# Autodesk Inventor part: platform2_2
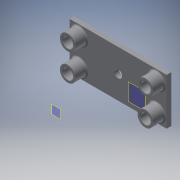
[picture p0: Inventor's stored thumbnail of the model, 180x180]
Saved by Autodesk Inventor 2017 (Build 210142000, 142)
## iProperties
Created: 2017-05
Part Number: platform2_2
Material: Generic
Document SubType Name: Modeling
Designer: 1717440
Density: 1 g/cm^3
Appearance: Default
Author: 1717440
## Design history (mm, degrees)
workplane "Work Plane1"
workplane "Work Plane4"
workplane "Work Plane2"
workplane "Work Plane3"
sketch "Sketch2"
  geometry: L1 (38.448, -43.362)-(38.448, 16.638); L2 (-86.552, 16.638)-(-86.552, -43.362); L3 (38.448, 16.638)-(-86.552, -43.362); L4 (-86.552, 16.638)-(38.448, -43.362); L5 (38.448, -43.362)-(-86.552, -43.362); L6 (38.448, 16.638)-(-86.552, 16.638); L7 (-25.603, -14.224)-(-22.5, -14.224); L8 (-22.5, -14.224)-(-22.5, -12.5); L9 (-22.5, -12.5)-(-25.603, -12.5); L10 (-25.603, -12.5)-(-25.603, -14.224); L11 (-22.5, -14.224)-(-25.603, -12.5); 2 further points
  constraints: 22 end point, 3 horizontal, 3 perpendicular, 2 midpoint, 2 parallel
  dimensions: "d11" = 125 distance of L1.start L2.end; "d12" = 60 distance of L2.start L2.end
extrude "Extrusion7" join sketch "Sketch2" distance "d20" = 6; taper "d21" = 0 deg
workplane "Work Plane5"
sketch "Sketch7"
  geometry: L1 (38.448, 43.362)-(38.448, -16.638) reference; L2 (-86.552, 43.362)-(38.448, 43.362) reference; L3 (-86.552, -16.638)-(-86.552, 43.362) reference; L4 (38.448, -16.638)-(-86.552, -16.638) reference; L5 (-74.052, 30.862)-(25.948, 30.862); L6 (25.948, 30.862)-(25.948, -4.138); L7 (25.948, -4.138)-(-74.052, -4.138); L8 (-74.052, -4.138)-(-74.052, 30.862); C1 r 6.425 at (-74.052, 30.862); C2 r 6.425 at (25.948, -4.138); C3 r 6.425 at (-74.052, -4.138); C4 r 6.425 at (25.948, 30.862); C5 r 10 at (-74.052, -4.138); C6 r 10 at (-74.052, 30.862); C7 r 10 at (25.948, 30.862); C8 r 10 at (25.948, -4.138); 1 further point
  constraints: 9 coincident, 8 centre point, 8 end point, 1 point on line, 3 other
  dimensions: "d25" = 12.5 distance between parallel lines of L3 L8; "d26" = 12.85 diameter of C1 (= d28); "d27" = 12.85 diameter of C2 (= d28); "d28" = 12.85 diameter of C3; "d29" = 12.85 diameter of C4 (= d28); "d33" = 20 diameter of C5; "d34" = 20 diameter of C6; "d35" = 20 diameter of C7; "d36" = 20 diameter of C8
workplane "Work Plane6"
extrude "Extrusion10" join sketch "Sketch7" distance "d37" = 15; taper "d38" = 0 deg
fillet "Fillet3" dims "d39" = 2
fillet "Fillet4" dims "d40" = 1
sketch "Sketch8"
  geometry: L1 (38.448, 16.638)-(-86.552, 16.638) reference; L2 (38.448, 16.638)-(-86.552, 16.638) reference; L3 (38.448, -43.362)-(33.448, -43.362); L4 (-86.552, -43.362)-(38.448, -43.362) reference; L5 (-86.552, 16.638)-(-86.552, -43.362) reference; L6 (33.448, -43.362)-(-86.552, 16.638); L7 (38.448, 16.638)-(33.448, 16.638); L8 (33.448, 16.638)-(-86.552, -43.362); C1 r 5.1 at (-26.552, -13.362); 1 further point
  constraints: 8 end point, 2 point on line, 1 centre point, 1 midpoint
  dimensions: "d43" = 10.2 diameter of C1; "d49" = 5 distance of L3.start L3.end; "d50" = 5 distance of L1.start L7.end
extrude "Extrusion11" cut sketch "Sketch8" distance "d41" = 16; taper "d42" = 0 deg
sketch "Sketch9"
  geometry: L1 (-86.552, 16.638)-(-86.552, -43.362) reference; L2 (38.448, 16.638)-(-86.552, 16.638) reference; L3 (38.448, 16.638)-(-86.552, 16.638); L4 (-86.552, 16.638)-(-86.552, 9.338); L5 (-86.552, 9.338)-(38.448, 9.338); L6 (38.448, 9.338)-(38.448, 16.638); L7 (38.448, -43.362)-(38.448, 16.638) reference; L8 (38.448, -43.362)-(-86.552, -43.362); L9 (-86.552, -43.362)-(-86.552, -36.062); L10 (-86.552, -36.062)-(38.448, -36.062); L11 (38.448, -36.062)-(38.448, -43.362); 1 further point
  constraints: 16 end point, 4 parallel, 2 horizontal, 2 perpendicular, 2 point on line
  dimensions: "d44" = 7.3 distance of L4.end L3.end; "d45" = 7.3 distance of L8.end L9.end
extrude "Extrusion12" join sketch "Sketch9" distance "d46" = 5; taper "d47" = 0 deg
fillet "Fillet5" dims "d48" = 2
body "Solid1"
